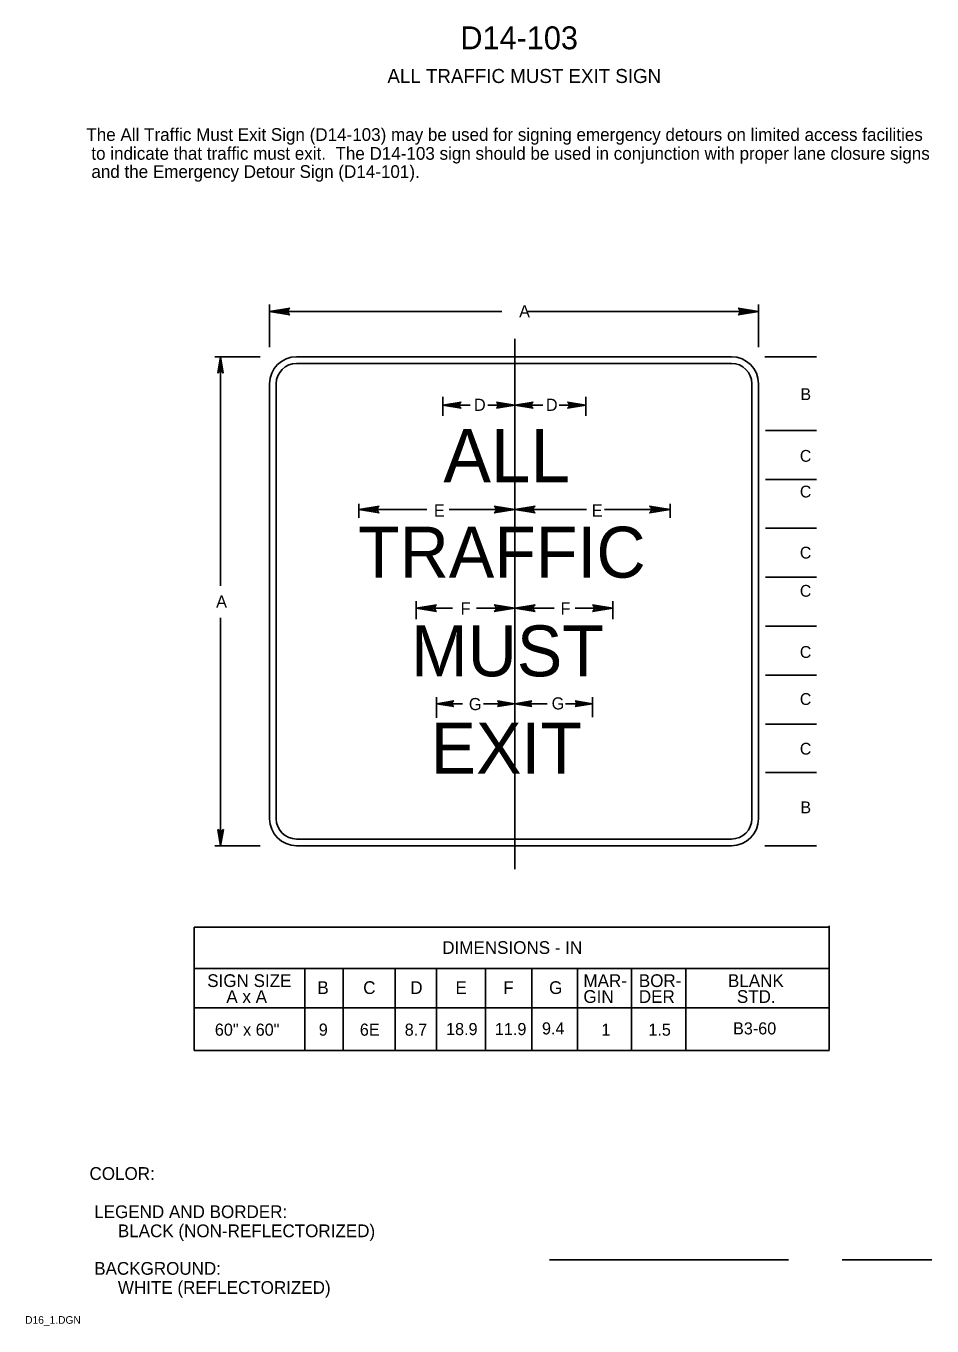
# Model space of a CAD drawing. Extents: x 0.013 to 0.191, y 0.004 to 0.259.
import ezdxf

# ---------------------------------------------------------------- set-up
doc = ezdxf.new("R2010")
doc.units = 0
doc.layers.add('1', color=7, linetype='Continuous')
doc.layers.add('3', color=7, linetype='Continuous')

# ---------------------------------------------------------------- blocks, each defined once
blk = doc.blocks.new('RARROW')
at = {"layer": '3'}
for p, q in [((-2.156, 0.285), (-2.2665, 0.384625)), ((-2.2665, 0.384625), (0, 0)), ((0, 0), (-2.2665, -0.379125)), ((-2.156, 0.285), (-2.075625, 0.12075)), ((0, 0), (-2.156, 0.285)), ((-2.14975, -0.2705), (0, 0)), ((-2.075625, 0.12075), (0, 0)), ((0, 0), (-2.074, -0.108)), ((-2.2665, -0.379125), (-2.14975, -0.2705)), ((-2.074, -0.108), (-2.14975, -0.2705))]:
    blk.add_line(p, q, dxfattribs=at)

msp = doc.modelspace()

# ---------------------------------------------------------------- linework, layer by layer
at = {"layer": '1'}
for p, q in [((0.10862, 0.19775), (0.10862, 0.09362)), ((0.11544, 0.01695), (0.16242, 0.01695)), ((0.17295, 0.01695), (0.19056, 0.01695))]:
    msp.add_line(p, q, dxfattribs=at)
at = {"layer": '3'}
for p, q in [((0.0605, 0.19612), (0.0605, 0.2045)), ((0.1565, 0.19612), (0.1565, 0.2045)), ((0.10612, 0.20312), (0.0605, 0.20312)), ((0.111, 0.20312), (0.1565, 0.20312)), ((0.05863, 0.19425), (0.04975, 0.19425)), ((0.05088, 0.14925), (0.05088, 0.19425)), ((0.0658, 0.19425), (0.1512, 0.19425)), ((0.15775, 0.19425), (0.16787, 0.19425)), ((0.0658, 0.19295), (0.1512, 0.19295)), ((0.0605, 0.18895), (0.0605, 0.10355)), ((0.0605, 0.10355), (0.0605, 0.18895)), ((0.0605, 0.10355), (0.0605, 0.18895)), ((0.0618, 0.10355), (0.0618, 0.18895)), ((0.1552, 0.18895), (0.1552, 0.10355)), ((0.1565, 0.18895), (0.1565, 0.10355)), ((0.0945, 0.18263), (0.0945, 0.18638)), ((0.10862, 0.18263), (0.10862, 0.18638)), ((0.12262, 0.18263), (0.12262, 0.18638)), ((0.09988, 0.18475), (0.0945, 0.18475)), ((0.10862, 0.18475), (0.10338, 0.18475)), ((0.11413, 0.18475), (0.10862, 0.18475)), ((0.12262, 0.18475), (0.11738, 0.18475)), ((0.15788, 0.17975), (0.16787, 0.17975)), ((0.15788, 0.17012), (0.16787, 0.17012)), ((0.078, 0.16537), (0.078, 0.16262)), ((0.09137, 0.16425), (0.078, 0.16425)), ((0.09575, 0.16425), (0.10862, 0.16425)), ((0.10862, 0.16537), (0.10862, 0.16262)), ((0.12275, 0.16425), (0.10862, 0.16425)), ((0.12625, 0.16425), (0.13912, 0.16425)), ((0.13912, 0.16537), (0.13912, 0.16262)), ((0.15788, 0.16062), (0.16787, 0.16062)), ((0.15788, 0.151), (0.16787, 0.151)), ((0.08925, 0.14275), (0.08925, 0.14625)), ((0.10862, 0.14275), (0.10862, 0.14638)), ((0.12788, 0.14275), (0.12788, 0.14625)), ((0.05088, 0.143), (0.05088, 0.09825)), ((0.08925, 0.14488), (0.09638, 0.14488)), ((0.10113, 0.14488), (0.10862, 0.14488)), ((0.11638, 0.14488), (0.10862, 0.14488)), ((0.12788, 0.14488), (0.1205, 0.14488)), ((0.15788, 0.14138), (0.16787, 0.14138)), ((0.15788, 0.13175), (0.16787, 0.13175)), ((0.09325, 0.12337), (0.09325, 0.12738)), ((0.09325, 0.12613), (0.09838, 0.12613)), ((0.1025, 0.12613), (0.10862, 0.12613)), ((0.10862, 0.12375), (0.10862, 0.12738)), ((0.115, 0.12613), (0.10862, 0.12613)), ((0.12387, 0.12613), (0.11863, 0.12613)), ((0.12387, 0.1235), (0.12387, 0.12738)), ((0.15788, 0.12212), (0.16787, 0.12212)), ((0.15788, 0.11263), (0.16787, 0.11263)), ((0.1512, 0.09955), (0.0658, 0.09955)), ((0.05863, 0.09825), (0.04975, 0.09825)), ((0.1512, 0.09825), (0.0658, 0.09825)), ((0.15775, 0.09825), (0.16787, 0.09825)), ((0.04567, 0.08226), (0.04567, 0.05801)), ((0.04567, 0.08226), (0.17041, 0.08226)), ((0.17037, 0.0825), (0.17037, 0.05825)), ((0.17041, 0.07413), (0.04591, 0.07413)), ((0.07492, 0.07423), (0.07492, 0.05801)), ((0.06742, 0.07398), (0.06742, 0.05801)), ((0.08517, 0.07398), (0.08517, 0.05801)), ((0.0933, 0.07398), (0.0933, 0.05801)), ((0.10287, 0.07398), (0.10287, 0.05801)), ((0.11198, 0.07398), (0.11198, 0.05801)), ((0.12098, 0.07398), (0.12098, 0.05801)), ((0.13159, 0.07398), (0.13159, 0.05801)), ((0.14221, 0.07398), (0.14221, 0.05801)), ((0.04561, 0.06638), (0.17041, 0.06638)), ((0.04567, 0.05801), (0.17041, 0.05801))]:
    msp.add_line(p, q, dxfattribs=at)
for centre, radius, start, end in [((0.0658, 0.18895), 0.0053, 90, 180), ((0.1512, 0.18895), 0.0053, 0, 90), ((0.0658, 0.18895), 0.004, 90, 180), ((0.1512, 0.18895), 0.004, 0, 90), ((0.0658, 0.10355), 0.0053, 180, 270), ((0.0658, 0.10355), 0.004, 180, 270), ((0.1512, 0.10355), 0.0053, 270, 0), ((0.1512, 0.10355), 0.004, 270, 0)]:
    msp.add_arc(centre, radius, start, end, dxfattribs=at)

# ---------------------------------------------------------------- block references
for p, xscale, yscale, rotation in [((0.0605, 0.20312), 0.0017647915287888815, 0.0017457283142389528, 180), ((0.05088, 0.19425), 0.0014118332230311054, 0.0013965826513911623, 90), ((0.0945, 0.18475), 0.0015883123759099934, 0.0015711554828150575, 180), ((0.10862, 0.18475), 0.0015883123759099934, 0.0015711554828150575, 180), ((0.078, 0.16425), 0.0017647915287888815, 0.0017457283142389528, 180), ((0.10862, 0.16425), 0.0017647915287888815, 0.0017457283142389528, 180), ((0.08925, 0.14488), 0.0017647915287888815, 0.0017457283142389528, 180), ((0.10862, 0.14488), 0.0017647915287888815, 0.0017457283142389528, 180), ((0.09325, 0.12613), 0.0015000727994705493, -0.0014838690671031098, 180), ((0.10862, 0.12613), 0.0015000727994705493, 0.0014838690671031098, 180), ((0.05088, 0.09825), 0.0014118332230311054, 0.0013965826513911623, -90)]:
    msp.add_blockref('RARROW', p, dxfattribs=dict(at, xscale=xscale, yscale=yscale, rotation=rotation))
for p, xscale, yscale in [((0.1565, 0.20312), 0.0017647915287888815, 0.0017457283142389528), ((0.10862, 0.18475), 0.0015883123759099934, -0.0015711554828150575), ((0.12262, 0.18475), 0.0015883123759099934, -0.0015711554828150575), ((0.10862, 0.16425), 0.0017647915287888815, 0.0017457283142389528), ((0.13912, 0.16425), 0.0017647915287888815, -0.0017457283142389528), ((0.10862, 0.14488), 0.0017647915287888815, 0.0017457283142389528), ((0.12788, 0.14488), 0.0017647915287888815, -0.0017457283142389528), ((0.10862, 0.12613), 0.0015000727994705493, 0.0014838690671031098), ((0.12387, 0.12613), 0.0015000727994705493, 0.0014838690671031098)]:
    msp.add_blockref('RARROW', p, dxfattribs=dict(at, xscale=xscale, yscale=yscale))

# ---------------------------------------------------------------- texts
at = {"layer": '1'}
for s, height, p in [('D14-103', 0.0045, (0.09796, 0.25462)), ('ALL TRAFFIC MUST EXIT SIGN', 0.0027503, (0.08363, 0.248)), ('     The All Traffic Must Exit Sign (D14-103) may be used for signing emergency detours on limited access facilities', 0.00249975, (0.01988, 0.23663)), ('to indicate that traffic must exit.  The D14-103 sign should be used in conjunction with proper lane closure signs', 0.00249975, (0.0255, 0.23293)), ('and the Emergency Detour Sign (D14-101).', 0.0024998, (0.0255, 0.22936)), ('COLOR:', 0.0025, (0.02513, 0.03263)), (' LEGEND AND BORDER:', 0.0024998, (0.02513, 0.02513)), ('      BLACK (NON-REFLECTORIZED)', 0.0024998, (0.02513, 0.02138)), (' BACKGROUND:', 0.0024998, (0.02513, 0.014)), ('      WHITE (REFLECTORIZED)', 0.0024998, (0.02513, 0.01025)), ('D16_1.DGN', 0.0015, (0.0125, 0.00438))]:
    msp.add_text(s, height=height, dxfattribs=at).set_placement(p)
at = {"layer": '3'}
for s, height, p in [('A', 0.00237, (0.1095, 0.202)), ('B', 0.00232, (0.16475, 0.18575)), ('D', 0.00238, (0.10063, 0.18363)), ('D', 0.00238, (0.11475, 0.18363)), ('ALL', 0.010454, (0.09463, 0.16962)), ('C', 0.00232, (0.16462, 0.17363)), ('C', 0.00232, (0.16462, 0.16662)), ('E', 0.00238, (0.09275, 0.16287)), ('E', 0.00238, (0.12375, 0.16287)), ('TRAFFIC', 0.01, (0.07787, 0.15088)), ('C', 0.00232, (0.16462, 0.15463)), ('C', 0.00232, (0.16462, 0.14713)), ('A', 0.00238, (0.05, 0.145)), ('F', 0.00238, (0.098, 0.14363)), ('F', 0.00238, (0.11763, 0.14363)), ('MUST', 0.01, (0.08825, 0.1315)), ('C', 0.00232, (0.16462, 0.13512)), ('C', 0.00232, (0.16462, 0.12588)), ('G', 0.00238, (0.09963, 0.12487)), ('G', 0.00238, (0.11588, 0.125)), ('EXIT', 0.01, (0.09212, 0.11238)), ('C', 0.00232, (0.16462, 0.11613)), ('B', 0.00232, (0.16475, 0.10462)), ('DIMENSIONS - IN', 0.0024998, (0.0944, 0.077)), ('SIGN SIZE', 0.0025, (0.04825, 0.0705)), ('B', 0.0025, (0.06988, 0.06913)), ('C', 0.0025, (0.07888, 0.06913)), ('D', 0.0025, (0.08812, 0.06913)), ('E', 0.0025, (0.097, 0.06913)), ('F', 0.0025, (0.10637, 0.06913)), ('G', 0.0025, (0.11538, 0.06913)), ('MAR-', 0.0025, (0.12212, 0.0705)), ('BOR-', 0.0025, (0.133, 0.0705)), ('BLANK', 0.0025, (0.1505, 0.0705)), ('A x A', 0.0025, (0.052, 0.06738)), ('GIN', 0.0025, (0.12212, 0.06738)), ('DER', 0.0025, (0.133, 0.06738)), ('STD.', 0.0025, (0.15225, 0.06738)), ('60" x 60"', 0.002375, (0.04975, 0.06094)), ('9', 0.00238, (0.07015, 0.06094)), ('6E', 0.002375, (0.07822, 0.06094)), ('8.7', 0.002375, (0.08703, 0.06094)), ('18.9', 0.002375, (0.09515, 0.06106)), ('11.9', 0.002375, (0.10474, 0.06106)), ('9.4', 0.002375, (0.11398, 0.06119)), ('1', 0.00238, (0.12565, 0.06094)), ('1.5', 0.002375, (0.13487, 0.06094)), ('B3-60', 0.002375, (0.1515, 0.06119))]:
    msp.add_text(s, height=height, dxfattribs=at).set_placement(p)

doc.saveas('drawing.dxf')
